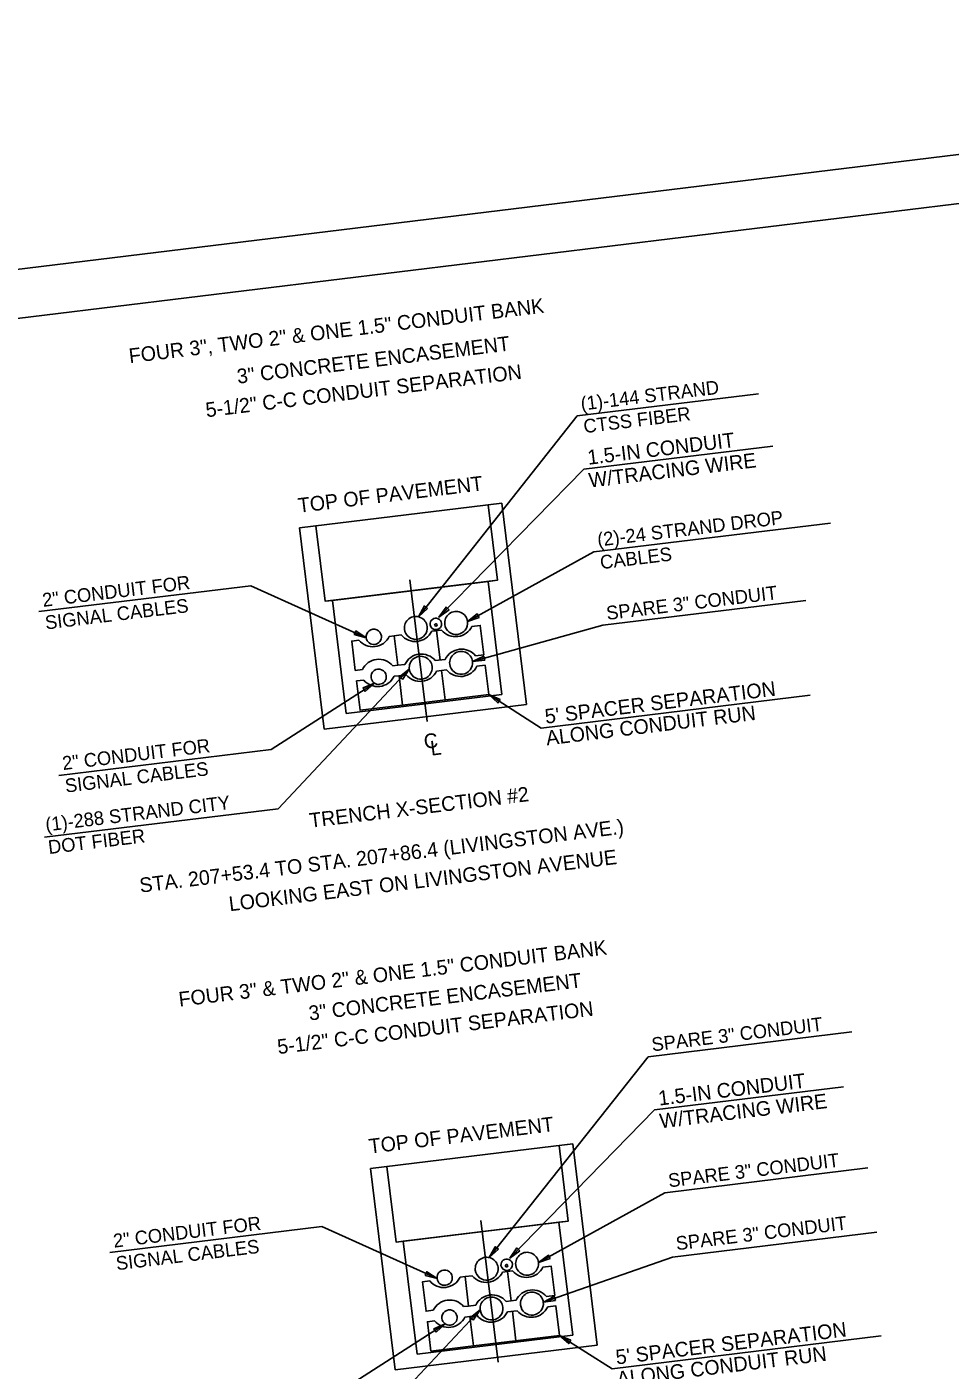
# Model space of a CAD drawing. Extents: x 91401 to 1830080, y 35587 to 712188.
# Drawn here: x 1828380 to 1828758, y 711584 to 712134 of the extents above; entities that cross this region are included whole.
import ezdxf

# ---------------------------------------------------------------- set-up
doc = ezdxf.new("R2010")
doc.units = 0
for name, color, linetype in [('Default', 7, 'Continuous'), ('SH_Border', 7, 'Continuous'), ('SH_Cut_Line', 7, 'Continuous'), ('SH_Text', 7, 'Continuous')]:
    doc.layers.add(name, color=color, linetype=linetype)

# ---------------------------------------------------------------- blocks, each defined once
blk = doc.blocks.new('POINT_DISPLAY')
at = {"layer": 'Default'}
blk.add_line((0, 0), (0, 0), dxfattribs=at)

msp = doc.modelspace()

# ---------------------------------------------------------------- linework, layer by layer
at = {"layer": 'SH_Border'}
msp.add_lwpolyline([(1827921.45, 711959.1), (1829172.16, 712111.82), (1829273.97, 711278.01), (1828023.26, 711125.29)], close=True, dxfattribs=at)
at = {"layer": 'SH_Cut_Line'}
msp.add_lwpolyline([(1827946.27, 711095.75), (1829296.25, 711260.58), (1829189.59, 712134.09), (1827839.62, 711969.26)], close=True, dxfattribs=at)
at = {"layer": 'SH_Text'}
for p, q in [((1828605.11, 711974.63), (1828679.39, 711983.7)), ((1828540.03, 711892.32), (1828605.11, 711974.63)), ((1828607.77, 711952.83), (1828685.14, 711962.27)), ((1828548.45, 711892.12), (1828607.77, 711952.83)), ((1828574.19, 711938.9), (1828568.6, 711938.21)), ((1828572.38, 711907.26), (1828568.6, 711938.21)), ((1828584.27, 711856.37), (1828574.19, 711938.9)), ((1828498.07, 711929.6), (1828491.36, 711928.78)), ((1828501.85, 711898.64), (1828498.07, 711929.6)), ((1828611.92, 711918.88), (1828708.82, 711930.71)), ((1828491.36, 711928.78), (1828501.43, 711846.26)), ((1828560.18, 711890.33), (1828611.92, 711918.88)), ((1828384.55, 711894.43), (1828471.45, 711905.05)), ((1828518.65, 711883.68), (1828471.45, 711905.05)), ((1828536.56, 711907.47), (1828543.65, 711849.39)), ((1828568.54, 711906.79), (1828574.2, 711860.47)), ((1828504.82, 711899.01), (1828501.85, 711898.64)), ((1828510.48, 711852.69), (1828504.82, 711899.01)), ((1828615.59, 711888.82), (1828698.72, 711898.97)), ((1828562.17, 711873.99), (1828615.59, 711888.82)), ((1828536.3, 711870.83), (1828482.61, 711813.62)), ((1828522.02, 711865.11), (1828479.65, 711837.9)), ((1828510.48, 711852.69), (1828574.2, 711860.47)), ((1828510.48, 711852.69), (1828574.2, 711860.47)), ((1828510.48, 711852.69), (1828574.2, 711860.47)), ((1828510.48, 711852.69), (1828574.2, 711860.47)), ((1828574.2, 711860.47), (1828510.48, 711852.69)), ((1828568.83, 711860.42), (1828590.32, 711846.7)), ((1828590.32, 711846.7), (1828700.52, 711860.15)), ((1828501.43, 711846.26), (1828584.27, 711856.37)), ((1828501.43, 711846.26), (1828584.27, 711856.37)), ((1828392.75, 711827.29), (1828479.65, 711837.9)), ((1828386.8, 711801.92), (1828482.61, 711813.62)), ((1828634.14, 711711.98), (1828717.51, 711722.16)), ((1828569.06, 711629.67), (1828634.14, 711711.98)), ((1828636.8, 711690.18), (1828714.17, 711699.63)), ((1828577.48, 711629.47), (1828636.8, 711690.18)), ((1828603.22, 711676.25), (1828597.63, 711675.57)), ((1828601.41, 711644.61), (1828597.63, 711675.57)), ((1828613.29, 711593.73), (1828603.22, 711676.25)), ((1828527.09, 711666.95), (1828520.38, 711666.14)), ((1828520.38, 711666.14), (1828530.46, 711583.61)), ((1828530.87, 711636), (1828527.09, 711666.95)), ((1828640.94, 711656.24), (1828724.07, 711666.39)), ((1828589.2, 711627.68), (1828640.94, 711656.24)), ((1828565.59, 711644.82), (1828572.68, 711586.74)), ((1828597.57, 711644.14), (1828603.22, 711597.82)), ((1828413.57, 711631.79), (1828500.48, 711642.4)), ((1828547.67, 711621.03), (1828500.48, 711642.4)), ((1828644.17, 711629.82), (1828727.83, 711640.04)), ((1828533.85, 711636.36), (1828530.87, 711636)), ((1828539.5, 711590.04), (1828533.85, 711636.36)), ((1828591.2, 711611.34), (1828644.17, 711629.82)), ((1828565.33, 711608.18), (1828511.64, 711550.98)), ((1828551.05, 711602.46), (1828508.67, 711575.26)), ((1828530.46, 711583.61), (1828613.29, 711593.73)), ((1828530.46, 711583.61), (1828613.29, 711593.73)), ((1828539.5, 711590.04), (1828603.22, 711597.82)), ((1828539.5, 711590.04), (1828603.22, 711597.82)), ((1828539.5, 711590.04), (1828603.22, 711597.82)), ((1828539.5, 711590.04), (1828603.22, 711597.82)), ((1828603.22, 711597.82), (1828539.5, 711590.04)), ((1828597.85, 711597.77), (1828619.34, 711584.05)), ((1828619.34, 711584.05), (1828729.55, 711597.51))]:
    msp.add_line(p, q, dxfattribs=at)
for points in [[(1828491.36, 711928.78), (1828561.9, 711937.39), (1828574.19, 711938.9), (1828574.19, 711938.9)], [(1828498.07, 711929.6), (1828501.85, 711898.64), (1828572.38, 711907.26), (1828568.6, 711938.21)], [(1828568.6, 711938.21), (1828572.38, 711907.26), (1828568.54, 711906.79)], [(1828584.27, 711856.37), (1828574.19, 711938.9)], [(1828501.43, 711846.26), (1828491.36, 711928.78)], [(1828504.82, 711899.01), (1828545.38, 711903.96), (1828568.54, 711906.79), (1828574.2, 711860.47)], [(1828504.82, 711899.01), (1828545.38, 711903.96), (1828568.54, 711906.79), (1828574.2, 711860.47)], [(1828504.82, 711899.01), (1828563.2, 711906.13), (1828568.54, 711906.79), (1828574.2, 711860.47)], [(1828504.82, 711899.01), (1828527.57, 711901.78), (1828568.54, 711906.79), (1828574.2, 711860.47)], [(1828510.48, 711852.69), (1828504.82, 711899.01)], [(1828510.48, 711852.69), (1828504.82, 711899.01)], [(1828549.52, 711886.86), (1828545.47, 711886.36)], [(1828547.5, 711886.61), (1828548.97, 711874.57)], [(1828563.44, 711876.34), (1828566.83, 711876.75), (1828565.36, 711888.79), (1828561.97, 711888.38)], [(1828515.62, 711882.72), (1828512.69, 711882.36), (1828514.16, 711870.32), (1828517.09, 711870.68)], [(1828530.09, 711884.48), (1828528.07, 711884.24)], [(1828533.02, 711884.84), (1828530.09, 711884.48), (1828531.56, 711872.45)], [(1828546.94, 711874.32), (1828550.99, 711874.82)], [(1828529.54, 711872.2), (1828531.56, 711872.45)], [(1828531.56, 711872.45), (1828534.49, 711872.8)], [(1828533.56, 711856.11), (1828568.83, 711860.42), (1828567.36, 711872.46), (1828563.97, 711872.04)], [(1828551.52, 711870.52), (1828547.46, 711870.03)], [(1828549.49, 711870.28), (1828550.96, 711858.24)], [(1828517.61, 711866.38), (1828514.69, 711866.03), (1828516.16, 711853.99), (1828533.56, 711856.11)], [(1828532.09, 711868.15), (1828530.06, 711867.9)], [(1828535.01, 711868.51), (1828532.09, 711868.15), (1828533.56, 711856.11)], [(1828520.38, 711666.14), (1828590.92, 711674.75), (1828603.22, 711676.25), (1828603.22, 711676.25)], [(1828527.09, 711666.95), (1828530.87, 711636), (1828601.41, 711644.61), (1828597.63, 711675.57)], [(1828597.63, 711675.57), (1828601.41, 711644.61), (1828597.57, 711644.14)], [(1828613.29, 711593.73), (1828603.22, 711676.25)], [(1828530.46, 711583.61), (1828520.38, 711666.14)], [(1828533.85, 711636.36), (1828574.41, 711641.31), (1828597.57, 711644.14), (1828603.22, 711597.82)], [(1828533.85, 711636.36), (1828574.41, 711641.31), (1828597.57, 711644.14), (1828603.22, 711597.82)], [(1828533.85, 711636.36), (1828592.22, 711643.49), (1828597.57, 711644.14), (1828603.22, 711597.82)], [(1828533.85, 711636.36), (1828556.6, 711639.14), (1828597.57, 711644.14), (1828603.22, 711597.82)], [(1828539.5, 711590.04), (1828533.85, 711636.36)], [(1828539.5, 711590.04), (1828533.85, 711636.36)], [(1828559.12, 711621.84), (1828557.09, 711621.59)], [(1828562.04, 711622.19), (1828559.12, 711621.84), (1828560.59, 711609.8)], [(1828578.55, 711624.21), (1828574.49, 711623.71)], [(1828576.52, 711623.96), (1828577.99, 711611.92)], [(1828592.47, 711613.69), (1828595.86, 711614.11), (1828594.39, 711626.14), (1828591, 711625.73)], [(1828544.64, 711620.07), (1828541.72, 711619.71), (1828543.19, 711607.67), (1828546.11, 711608.03)], [(1828575.96, 711611.68), (1828580.02, 711612.17)], [(1828558.56, 711609.55), (1828560.59, 711609.8)], [(1828561.11, 711605.51), (1828559.09, 711605.26)], [(1828560.59, 711609.8), (1828563.51, 711610.16)], [(1828564.04, 711605.86), (1828561.11, 711605.51), (1828562.58, 711593.47)], [(1828562.58, 711593.47), (1828597.85, 711597.77), (1828596.38, 711609.81), (1828592.99, 711609.4)], [(1828580.54, 711607.88), (1828576.49, 711607.38)], [(1828578.51, 711607.63), (1828579.98, 711595.59)], [(1828546.64, 711603.74), (1828543.71, 711603.38), (1828545.18, 711591.34), (1828562.58, 711593.47)]]:
    msp.add_lwpolyline(points, dxfattribs=at)
for points in [[(1828543.79, 711895.72), (1828542.48, 711896.76), (1828540.03, 711892.32)], [(1828552.57, 711895.08), (1828551.38, 711896.25), (1828548.45, 711892.12)], [(1828564.96, 711892.02), (1828564.15, 711893.47), (1828560.18, 711890.33)], [(1828513.75, 711884.98), (1828514.44, 711886.5), (1828518.65, 711883.68)], [(1828567.21, 711874.53), (1828566.77, 711876.13), (1828562.17, 711873.99)], [(1828533.49, 711866.61), (1828532.27, 711867.75), (1828536.3, 711870.83)], [(1828518.26, 711861.71), (1828517.36, 711863.11), (1828522.02, 711865.11)], [(1828573.49, 711858.42), (1828572.59, 711857.02), (1828568.83, 711860.42)], [(1828572.81, 711633.08), (1828571.5, 711634.11), (1828569.06, 711629.67)], [(1828581.59, 711632.43), (1828580.41, 711633.61), (1828577.48, 711629.47)], [(1828594.04, 711629.21), (1828593.28, 711630.69), (1828589.2, 711627.68)], [(1828542.77, 711622.34), (1828543.46, 711623.85), (1828547.67, 711621.03)], [(1828596.21, 711612.09), (1828595.7, 711613.67), (1828591.2, 711611.34)], [(1828562.51, 711603.97), (1828561.3, 711605.11), (1828565.33, 711608.18)], [(1828547.29, 711599.06), (1828546.39, 711600.46), (1828551.05, 711602.46)], [(1828602.51, 711595.78), (1828601.61, 711594.38), (1828597.85, 711597.77)]]:
    msp.add_lwpolyline(points, close=True, dxfattribs=at)
for centre, radius, start, end in [((1828538.97, 711887.74), 4.7, 6.9614, 186.9614), ((1828547.17, 711889.35), 2.35, 6.9614, 186.9614), ((1828555.51, 711889.76), 4.7, 6.9614, 186.9614), ((1828521.76, 711884.06), 3.13, 6.9614, 186.9614), ((1828538.76, 711889.6), 7.45, 219.6485, 334.2743), ((1828538.97, 711887.74), 4.7, 186.9614, 6.9614), ((1828547.17, 711889.35), 2.35, 186.9614, 6.9614), ((1828547.15, 711888.94), 0.5, 6.9614, 186.9614), ((1828547.15, 711888.94), 0.5, 186.9614, 6.9614), ((1828555.26, 711891.61), 7.45, 219.6485, 334.2743), ((1828555.51, 711889.76), 4.7, 186.9614, 6.9614), ((1828521.36, 711887.47), 7.45, 219.6485, 334.2743), ((1828521.76, 711884.06), 3.13, 186.9614, 6.9614), ((1828523.8, 711867.44), 7.45, 39.6485, 154.2743), ((1828541.2, 711869.57), 7.45, 39.6485, 154.2743), ((1828540.97, 711871.4), 4.7, 6.9614, 186.9614), ((1828557.71, 711871.58), 7.45, 39.6485, 154.2743), ((1828557.51, 711873.42), 4.7, 6.9614, 186.9614), ((1828523.75, 711867.72), 3.13, 6.9614, 186.9614), ((1828540.75, 711873.26), 7.45, 219.6485, 334.2743), ((1828540.97, 711871.4), 4.7, 186.9614, 6.9614), ((1828557.26, 711875.28), 7.45, 219.6485, 334.2743), ((1828557.51, 711873.42), 4.7, 186.9614, 6.9614), ((1828523.35, 711871.14), 7.45, 219.6485, 334.2743), ((1828523.75, 711867.72), 3.13, 186.9614, 6.9614), ((1828568, 711625.09), 4.7, 6.9614, 186.9614), ((1828576.19, 711626.7), 2.35, 6.9614, 186.9614), ((1828576.19, 711626.7), 2.35, 186.9614, 6.9614), ((1828576.17, 711626.29), 0.5, 6.9614, 186.9614), ((1828584.54, 711627.11), 4.7, 6.9614, 186.9614), ((1828584.54, 711627.11), 4.7, 186.9614, 6.9614), ((1828550.38, 711624.82), 7.45, 219.6485, 334.2743), ((1828550.78, 711621.41), 3.13, 6.9614, 186.9614), ((1828550.78, 711621.41), 3.13, 186.9614, 6.9614), ((1828567.78, 711626.95), 7.45, 219.6485, 334.2743), ((1828568, 711625.09), 4.7, 186.9614, 6.9614), ((1828576.17, 711626.29), 0.5, 186.9614, 6.9614), ((1828584.28, 711628.96), 7.45, 219.6485, 334.2743), ((1828586.73, 711608.94), 7.45, 39.6485, 154.2743), ((1828552.82, 711604.8), 7.45, 39.6485, 154.2743), ((1828570.23, 711606.92), 7.45, 39.6485, 154.2743), ((1828569.99, 711608.75), 4.7, 6.9614, 186.9614), ((1828586.53, 711610.77), 4.7, 6.9614, 186.9614), ((1828586.53, 711610.77), 4.7, 186.9614, 6.9614), ((1828552.37, 711608.49), 7.45, 219.6485, 334.2743), ((1828552.78, 711605.07), 3.13, 6.9614, 186.9614), ((1828552.78, 711605.07), 3.13, 186.9614, 6.9614), ((1828569.78, 711610.62), 7.45, 219.6485, 334.2743), ((1828569.99, 711608.75), 4.7, 186.9614, 6.9614), ((1828586.28, 711612.63), 7.45, 219.6485, 334.2743)]:
    msp.add_arc(centre, radius, start, end, dxfattribs=at)

# ---------------------------------------------------------------- block references
at = {"layer": 'SH_Text', "xscale": 1.5748, "yscale": 1.5748000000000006, "rotation": 6.96142799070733}
for p in [(1828542.82, 711856.24), (1828571.84, 711593.59)]:
    msp.add_blockref('POINT_DISPLAY', p, dxfattribs=at)

# ---------------------------------------------------------------- texts
at = {"layer": 'SH_Text'}
for s, height, p in [('FOUR 3", TWO 2" & ONE 1.5" CONDUIT BANK', 6, (1828421.8, 711996.22)), ('3" CONCRETE ENCASEMENT', 6, (1828466.07, 711987.82)), ('5-1/2" C-C CONDUIT SEPARATION', 6, (1828453.24, 711974.06)), ('(1)-144 STRAND', 5.6, (1828606.85, 711976.8)), ('CTSS FIBER', 5.6, (1828607.99, 711967.54)), ('1.5-IN CONDUIT', 6, (1828609.65, 711954.58)), ('W/TRACING WIRE', 6, (1828610.16, 711945.23)), ('TOP OF PAVEMENT', 6, (1828491.06, 711934.9)), ('(2)-24 STRAND DROP ', 5.6, (1828613.66, 711921.06)), ('CABLES', 5.6, (1828614.79, 711911.79)), ('2" CONDUIT FOR ', 5.6, (1828386.32, 711896.34)), ('SPARE 3" CONDUIT', 5.6, (1828617.33, 711890.99)), ('SIGNAL CABLES', 5.6, (1828387.46, 711887.07)), ("5' SPACER SEPARATION", 6, (1828592.2, 711848.45)), ('ALONG CONDUIT RUN', 6, (1828592.64, 711839.58)), ('2" CONDUIT FOR ', 5.6, (1828394.49, 711829.46)), ('C', 6, (1828542.61, 711838.15)), ('L', 6, (1828545.3, 711835.36)), ('SIGNAL CABLES', 5.6, (1828395.62, 711820.2)), ('TRENCH X-SECTION #2', 6, (1828495.73, 711805.8)), ('(1)-288 STRAND CITY ', 5.6, (1828387.58, 711804.3)), ('STA. 207+53.4 TO STA. 207+86.4 (LIVINGSTON AVE.)', 6, (1828426.15, 711779.21)), ('DOT FIBER', 5.6, (1828388.71, 711795.03)), ('LOOKING EAST ON LIVINGSTON AVENUE', 6, (1828462.77, 711771.59)), ('FOUR 3" & TWO 2" & ONE 1.5" CONDUIT BANK', 6, (1828442.19, 711732.49)), ('3" CONCRETE ENCASEMENT', 6, (1828495.44, 711726.8)), ('5-1/2" C-C CONDUIT SEPARATION', 6, (1828482.61, 711713.04)), ('SPARE 3" CONDUIT', 5.6, (1828635.88, 711714.16)), ('1.5-IN CONDUIT', 6, (1828638.68, 711691.94)), ('W/TRACING WIRE', 6, (1828639.18, 711682.59)), ('TOP OF PAVEMENT', 6, (1828520.09, 711672.25)), ('SPARE 3" CONDUIT', 5.6, (1828642.69, 711658.41)), ('2" CONDUIT FOR ', 5.6, (1828415.35, 711633.69)), ('SPARE 3" CONDUIT', 5.6, (1828645.83, 711632.63)), ('SIGNAL CABLES', 5.6, (1828416.48, 711624.43)), ("5' SPACER SEPARATION", 6, (1828621.22, 711585.81)), ('ALONG CONDUIT RUN', 6, (1828621.67, 711576.93))]:
    msp.add_text(s, height=height, rotation=6.9614, dxfattribs=at).set_placement(p)

doc.saveas('drawing.dxf')
